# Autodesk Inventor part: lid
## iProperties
Created: 2007-03
Part Number: lid
Document SubType Name: Modeling
Designer: NEV96356
Density: 1 g/cm^3
Author: NEV96356
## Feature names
1. Extrusion1
2. Extrusion2
3. Hole1
